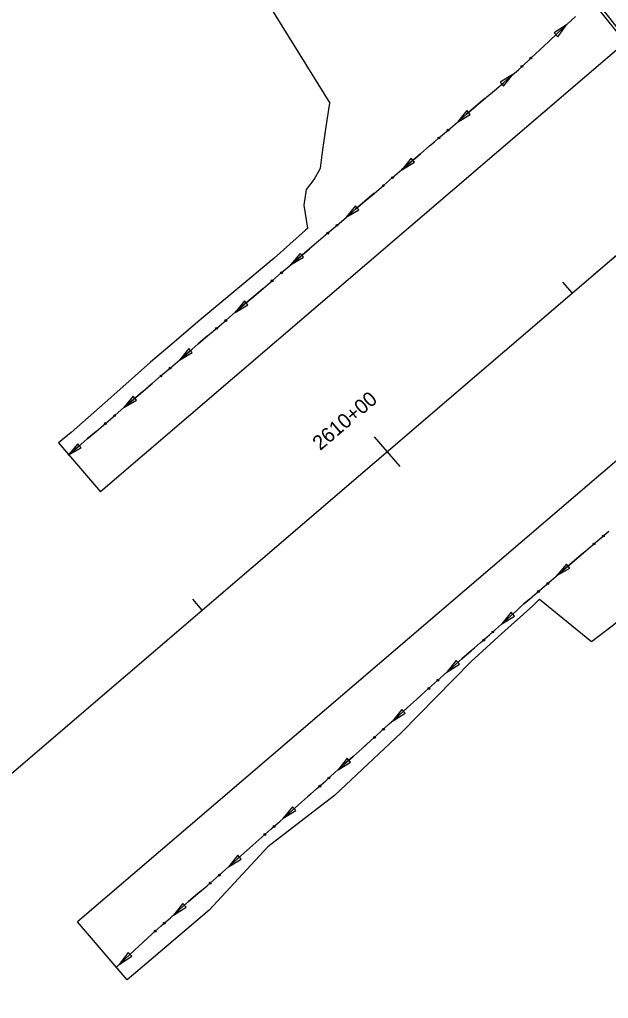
# Model space of a CAD drawing. Extents: x 916431 to 921570, y 1763982 to 1768032.
# Drawn here: x 918751.6 to 918993.2, y 1764755.3 to 1765157.2 of the extents above; entities that cross this region are included whole.
import ezdxf

# ---------------------------------------------------------------- set-up
doc = ezdxf.new("R2010")
doc.units = 0
for name, color, linetype in [('B-Super-Deck', 7, 'Continuous'), ('Default', 7, 'Continuous'), ('R_Horz Alg', 7, 'Continuous'), ('R_Horz Alg Stationing', 7, 'Continuous'), ('R_Proposed Const Limits', 7, 'Continuous'), ('R_Proposed Road', 7, 'Continuous'), ('R_Shld', 7, 'Continuous'), ('R_Special Ditch', 7, 'Continuous')]:
    doc.layers.add(name, color=color, linetype=linetype)

msp = doc.modelspace()

# ---------------------------------------------------------------- linework, layer by layer
at = {"layer": 'B-Super-Deck'}
for radius in [11442.91, 11444.16]:
    msp.add_arc((910020.66, 1758054.88), radius, 37.482752, 38.493599, dxfattribs=at)
at = {"layer": 'Default'}
msp.add_line((918987.45, 1765052.64), (919007.17, 1765069.53), dxfattribs=at)
at = {"layer": 'R_Horz Alg'}
msp.add_line((918522.67, 1764654.46), (919661.81, 1765630.35), dxfattribs=at)
msp.add_arc((910020.66, 1758054.88), 11459.16, 34.999167, 38.976944, dxfattribs=at)
at = {"layer": 'R_Horz Alg Stationing'}
for points in [[(918974.42, 1765049.37), (918978.33, 1765044.82)], [(918897.18, 1764985.83), (918907.59, 1764973.68)], [(918822.54, 1764919.25), (918826.44, 1764914.7)]]:
    msp.add_lwpolyline(points, dxfattribs=at)
at = {"layer": 'R_Proposed Const Limits'}
for p, q in [((918767.63, 1764983.35), (918784.8, 1764963.3)), ((918795.77, 1764762.97), (918775.43, 1764786.72))]:
    msp.add_line(p, q, dxfattribs=at)
for points in [[(918663.54, 1765493.36), (918697.72, 1765422.89), (918728.86, 1765363.64), (918783.6, 1765276.66), (918878.88, 1765122.86)], [(918869.89, 1765071.62), (918868.36, 1765080.96), (918869.37, 1765087.46), (918870.82, 1765089.36), (918872.48, 1765091.52), (918875.05, 1765096.2), (918875.98, 1765102.8), (918876.91, 1765109.4), (918877.88, 1765115.96), (918878.88, 1765122.86)], [(918869.89, 1765071.62), (918868.92, 1765070.75), (918856.11, 1765059.18), (918840.4, 1765046.16), (918824.7, 1765033.13), (918815.04, 1765024.81), (918805.38, 1765016.49), (918789.07, 1765002.08), (918772.76, 1764987.66), (918767.63, 1764983.35)], [(918964.92, 1764919.17), (918986.24, 1764901.85), (918990.25, 1764904.86), (918994.26, 1764907.86), (918998.17, 1764910.98), (919002.08, 1764914.11), (919006.06, 1764917.14), (919010, 1764920.23), (919013.83, 1764923.44), (919018.04, 1764926.21), (919022.29, 1764928.94), (919026.46, 1764931.76), (919030.61, 1764934.6), (919036.49, 1764935.42), (919043.14, 1764935.34), (919049.87, 1764935.17), (919056.56, 1764935.05), (919063.18, 1764935), (919069.62, 1764935.18), (919071.4, 1764935.3)], [(918964.92, 1764919.17), (918962.22, 1764916.49), (918949.55, 1764905.08), (918936.88, 1764893.67), (918922.51, 1764878.97), (918908.13, 1764864.27), (918894.47, 1764851.4), (918880.81, 1764838.53), (918867.15, 1764827.99), (918853.49, 1764817.46), (918841.47, 1764804.49), (918829.45, 1764791.51), (918814.76, 1764779.03), (918800.08, 1764766.54), (918795.77, 1764762.97)]]:
    msp.add_lwpolyline(points, dxfattribs=at)
at = {"layer": 'R_Proposed Road'}
for radius, start in [(11470.16, 34.999167), (11448.16, 35.073221)]:
    msp.add_arc((910020.66, 1758054.88), radius, start, 38.976944, dxfattribs=at)
at = {"layer": 'R_Shld'}
for p, q in [((919202.49, 1765321.13), (918784.8, 1764963.3)), ((919160.46, 1765116.57), (918775.43, 1764786.72))]:
    msp.add_line(p, q, dxfattribs=at)
for radius, start in [(11474.16, 34.999167), (11444.16, 35.078536)]:
    msp.add_arc((910020.66, 1758054.88), radius, start, 38.976944, dxfattribs=at)
at = {"layer": 'R_Special Ditch'}
for p, q in [((918976.08, 1765155.05), (918970.97, 1765151.73)), ((918972.42, 1765150.18), (918976.08, 1765155.05)), ((918970.97, 1765151.73), (918972.42, 1765150.18)), ((918954.05, 1765134.63), (918948.81, 1765131.53)), ((918950.18, 1765129.93), (918954.05, 1765134.63)), ((918948.81, 1765131.53), (918950.18, 1765129.93)), ((918935.14, 1765119.82), (918931.27, 1765115.11)), ((918936.51, 1765118.21), (918935.14, 1765119.82)), ((918931.27, 1765115.11), (918936.51, 1765118.21)), ((918912.33, 1765100.28), (918908.46, 1765095.57)), ((918913.7, 1765098.67), (918912.33, 1765100.28)), ((918908.46, 1765095.57), (918913.7, 1765098.67)), ((918889.51, 1765080.74), (918885.65, 1765076.03)), ((918890.89, 1765079.13), (918889.51, 1765080.74)), ((918885.65, 1765076.03), (918890.89, 1765079.13)), ((918866.7, 1765061.19), (918862.83, 1765056.49)), ((918862.83, 1765056.49), (918868.08, 1765059.59)), ((918868.08, 1765059.59), (918866.7, 1765061.19)), ((918843.89, 1765041.65), (918840.02, 1765036.94)), ((918840.02, 1765036.94), (918845.27, 1765040.04)), ((918845.27, 1765040.04), (918843.89, 1765041.65)), ((918821.08, 1765022.11), (918817.21, 1765017.4)), ((918817.21, 1765017.4), (918822.46, 1765020.5)), ((918822.46, 1765020.5), (918821.08, 1765022.11)), ((918798.27, 1765002.57), (918794.4, 1764997.86)), ((918794.4, 1764997.86), (918799.64, 1765000.96)), ((918799.64, 1765000.96), (918798.27, 1765002.57)), ((918775.46, 1764983.02), (918771.59, 1764978.32)), ((918771.59, 1764978.32), (918776.83, 1764981.42)), ((918776.83, 1764981.42), (918775.46, 1764983.02)), ((918976, 1764933.61), (918972.13, 1764928.9)), ((918972.13, 1764928.9), (918977.38, 1764932)), ((918977.38, 1764932), (918976, 1764933.61)), ((918953.33, 1764913.88), (918949.55, 1764909.1)), ((918949.55, 1764909.1), (918954.74, 1764912.3)), ((918954.74, 1764912.3), (918953.33, 1764913.88)), ((918930.76, 1764894.05), (918926.99, 1764889.27)), ((918926.99, 1764889.27), (918932.17, 1764892.48)), ((918932.17, 1764892.48), (918930.76, 1764894.05)), ((918908.43, 1764873.96), (918904.67, 1764869.17)), ((918904.67, 1764869.17), (918909.84, 1764872.39)), ((918909.84, 1764872.39), (918908.43, 1764873.96)), ((918886.05, 1764853.93), (918882.28, 1764849.15)), ((918882.28, 1764849.15), (918887.46, 1764852.35)), ((918887.46, 1764852.35), (918886.05, 1764853.93)), ((918863.6, 1764833.99), (918859.78, 1764829.25)), ((918859.78, 1764829.25), (918864.99, 1764832.4)), ((918864.99, 1764832.4), (918863.6, 1764833.99)), ((918841.12, 1764814.06), (918837.34, 1764809.28)), ((918837.34, 1764809.28), (918842.52, 1764812.48)), ((918842.52, 1764812.48), (918841.12, 1764814.06)), ((918818.53, 1764794.27), (918814.72, 1764789.51)), ((918819.93, 1764792.68), (918818.53, 1764794.27)), ((918814.72, 1764789.51), (918819.93, 1764792.68)), ((918796.21, 1764774.13), (918792.53, 1764769.27)), ((918797.65, 1764772.58), (918796.21, 1764774.13)), ((918792.53, 1764769.27), (918797.65, 1764772.58))]:
    msp.add_line(p, q, dxfattribs=at)
for points in [[(918942.66, 1765124.87), (918943.12, 1765125.26), (918943.35, 1765125.46), (918946.46, 1765128.13), (918950.26, 1765131.38), (918954.05, 1765134.63), (918955.57, 1765135.93), (918956.33, 1765136.58), (918957.79, 1765137.95), (918961.45, 1765141.37), (918965.11, 1765144.79), (918968.76, 1765148.2), (918972.41, 1765151.62), (918976.07, 1765155.04), (918979.71, 1765158.47)], [(918965.13, 1765144.8), (918968.76, 1765148.2), (918972.41, 1765151.62), (918976.07, 1765155.04), (918976.08, 1765155.05)], [(918965.1, 1765144.78), (918965.11, 1765144.79), (918965.13, 1765144.8)], [(918942.66, 1765124.87), (918943.12, 1765125.26), (918943.35, 1765125.46), (918946.46, 1765128.13), (918950.26, 1765131.38), (918954.05, 1765134.63)], [(918771.79, 1764978.49), (918775.59, 1764981.74), (918779.38, 1764985), (918783.18, 1764988.25), (918786.98, 1764991.5), (918790.78, 1764994.75), (918794.57, 1764998.01), (918798.37, 1765001.26), (918802.17, 1765004.51), (918805.96, 1765007.77), (918809.76, 1765011.02), (918813.56, 1765014.27), (918817.36, 1765017.53), (918821.15, 1765020.78), (918824.95, 1765024.03), (918828.75, 1765027.28), (918832.54, 1765030.54), (918836.34, 1765033.79), (918840.14, 1765037.04), (918843.94, 1765040.3), (918847.73, 1765043.55), (918851.53, 1765046.8), (918855.33, 1765050.05), (918859.12, 1765053.31), (918862.92, 1765056.56), (918866.72, 1765059.81), (918870.52, 1765063.07), (918874.31, 1765066.32), (918878.11, 1765069.57), (918881.91, 1765072.83), (918883.69, 1765074.35), (918885.7, 1765076.08), (918889.5, 1765079.33), (918893.3, 1765082.58), (918897.1, 1765085.84), (918900.89, 1765089.09), (918904.69, 1765092.34), (918908.49, 1765095.6), (918912.28, 1765098.85), (918916.08, 1765102.1), (918919.88, 1765105.36), (918921.82, 1765107.02), (918923.68, 1765108.61), (918927.47, 1765111.86), (918931.27, 1765115.11), (918935.07, 1765118.37), (918938.86, 1765121.62), (918942.66, 1765124.87)], [(918942.66, 1765124.87), (918938.86, 1765121.62), (918935.07, 1765118.37), (918931.27, 1765115.11)], [(918919.85, 1765105.33), (918916.08, 1765102.1), (918912.28, 1765098.85), (918908.49, 1765095.6), (918908.46, 1765095.57)], [(918919.88, 1765105.36), (918919.85, 1765105.33)], [(918897.04, 1765085.79), (918893.3, 1765082.58), (918889.5, 1765079.33), (918885.7, 1765076.08), (918885.65, 1765076.03)], [(918897.07, 1765085.81), (918897.04, 1765085.79)], [(918874.23, 1765066.25), (918870.52, 1765063.07), (918866.72, 1765059.81), (918862.92, 1765056.56), (918862.83, 1765056.49)], [(918874.25, 1765066.27), (918874.23, 1765066.25)], [(918851.41, 1765046.7), (918847.73, 1765043.55), (918843.94, 1765040.3), (918840.14, 1765037.04), (918840.02, 1765036.94)], [(918851.44, 1765046.73), (918851.41, 1765046.7)], [(918828.6, 1765027.16), (918824.95, 1765024.03), (918821.15, 1765020.78), (918817.36, 1765017.53), (918817.21, 1765017.4)], [(918828.63, 1765027.19), (918828.6, 1765027.16)], [(918805.79, 1765007.62), (918802.17, 1765004.51), (918798.37, 1765001.26), (918794.57, 1764998.01), (918794.4, 1764997.86)], [(918805.82, 1765007.64), (918805.79, 1765007.62)], [(918782.98, 1764988.08), (918779.38, 1764985), (918775.59, 1764981.74), (918771.79, 1764978.49)], [(918783.01, 1764988.1), (918782.98, 1764988.08)], [(918791.33, 1764768.16), (918795, 1764771.56), (918798.65, 1764774.98), (918802.31, 1764778.4), (918805.97, 1764781.81), (918809.71, 1764785.13), (918813.48, 1764788.41), (918817.23, 1764791.72), (918820.97, 1764795.05), (918824.76, 1764798.3), (918828.56, 1764801.56), (918832.33, 1764804.84), (918836.08, 1764808.15), (918839.81, 1764811.48), (918843.54, 1764814.81), (918847.26, 1764818.16), (918850.98, 1764821.5), (918854.73, 1764824.81), (918858.48, 1764828.11), (918862.24, 1764831.4), (918866.01, 1764834.7), (918869.77, 1764837.99), (918873.51, 1764841.31), (918877.23, 1764844.65), (918880.96, 1764847.98), (918884.7, 1764851.31), (918888.43, 1764854.63), (918892.18, 1764857.94), (918895.89, 1764861.3), (918899.61, 1764864.64), (918903.34, 1764867.98), (918907.06, 1764871.31), (918910.77, 1764874.67), (918914.48, 1764878.03), (918918.2, 1764881.37), (918921.92, 1764884.71), (918925.63, 1764888.06), (918929.37, 1764891.39), (918933.13, 1764894.68), (918936.9, 1764897.97), (918940.67, 1764901.25), (918944.44, 1764904.54), (918948.17, 1764907.87), (918951.9, 1764911.2), (918955.6, 1764914.56), (918957.08, 1764915.91), (918958.55, 1764917.27), (918959.31, 1764917.92), (918960.07, 1764918.57), (918960.83, 1764919.22), (918963.11, 1764921.17), (918966.9, 1764924.42), (918970.7, 1764927.68), (918974.5, 1764930.93), (918978.3, 1764934.18), (918982.09, 1764937.44), (918985.89, 1764940.69), (918989.69, 1764943.94), (918993.48, 1764947.19)], [(918983.53, 1764938.66), (918982.09, 1764937.44), (918978.3, 1764934.18), (918974.5, 1764930.93), (918972.13, 1764928.9)], [(918983.55, 1764938.69), (918983.53, 1764938.66)], [(918960.71, 1764919.12), (918960.07, 1764918.57), (918959.31, 1764917.92), (918958.55, 1764917.27), (918957.08, 1764915.91), (918955.6, 1764914.56), (918951.9, 1764911.2), (918949.55, 1764909.1)], [(918960.74, 1764919.14), (918960.71, 1764919.12)], [(918938.27, 1764899.16), (918936.9, 1764897.97), (918933.13, 1764894.68), (918929.37, 1764891.39), (918926.99, 1764889.27)], [(918938.3, 1764899.18), (918938.27, 1764899.16)], [(918915.81, 1764879.22), (918914.48, 1764878.03), (918910.77, 1764874.67), (918907.06, 1764871.31), (918904.67, 1764869.17)], [(918915.83, 1764879.24), (918915.81, 1764879.22)], [(918893.48, 1764859.12), (918892.18, 1764857.94), (918888.43, 1764854.63), (918884.7, 1764851.31), (918882.28, 1764849.15)], [(918893.51, 1764859.14), (918893.48, 1764859.12)], [(918871.06, 1764839.14), (918869.77, 1764837.99), (918866.01, 1764834.7), (918862.24, 1764831.4), (918859.78, 1764829.25)], [(918871.09, 1764839.16), (918871.06, 1764839.14)], [(918848.51, 1764819.28), (918847.26, 1764818.16), (918843.54, 1764814.81), (918839.81, 1764811.48), (918837.34, 1764809.28)], [(918848.54, 1764819.31), (918848.51, 1764819.28)], [(918826.02, 1764799.38), (918824.76, 1764798.3), (918820.97, 1764795.05), (918817.23, 1764791.72), (918814.72, 1764789.51)], [(918826.05, 1764799.41), (918826.02, 1764799.38)], [(918803.5, 1764779.5), (918802.31, 1764778.4), (918798.65, 1764774.98), (918795, 1764771.56), (918792.53, 1764769.27)], [(918803.53, 1764779.53), (918803.5, 1764779.51)]]:
    msp.add_lwpolyline(points, dxfattribs=at)
for centre in [(918961.43, 1765141.4), (918957.77, 1765137.98), (918927.49, 1765111.83), (918923.69, 1765108.57), (918904.68, 1765092.29), (918900.88, 1765089.03), (918881.87, 1765072.74), (918878.06, 1765069.49), (918859.06, 1765053.2), (918855.25, 1765049.94), (918836.24, 1765033.66), (918832.44, 1765030.4), (918813.43, 1765014.12), (918809.63, 1765010.86), (918786.82, 1764991.32), (918790.62, 1764994.57), (918991.17, 1764945.16), (918987.36, 1764941.9), (918968.36, 1764925.62), (918964.55, 1764922.36), (918942.08, 1764902.43), (918945.84, 1764905.74), (918919.57, 1764882.55), (918923.29, 1764885.9), (918897.24, 1764862.46), (918900.96, 1764865.8), (918874.83, 1764842.45), (918878.56, 1764845.79), (918852.28, 1764822.6), (918856.04, 1764825.92), (918833.62, 1764805.93), (918829.85, 1764802.63), (918810.98, 1764786.19), (918807.22, 1764782.87)]:
    msp.add_circle(centre, 0.375, dxfattribs=at)

# ---------------------------------------------------------------- texts
at = {"layer": 'R_Horz Alg Stationing'}
msp.add_text('2610+00', height=6, rotation=40.5864, dxfattribs=at).set_placement((918874.99, 1764980))

doc.saveas('drawing.dxf')
